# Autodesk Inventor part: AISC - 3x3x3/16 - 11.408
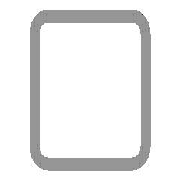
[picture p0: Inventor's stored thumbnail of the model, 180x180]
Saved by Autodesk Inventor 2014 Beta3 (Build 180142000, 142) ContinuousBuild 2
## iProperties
IsCustomPart: 1
Created: 2010-11
Part Number: AISC - 3x3x3/16 - 11.408
Material: Steel, Mild
Description: Tube
Document SubType Name: Modeling
Standard: ANSI
Designer: Beta-8540w
Standards Organization: ANSI
Language: en-US
Size Designation: 3x3x3/16
Categories: <MemberInstance><Categories><Category DisplayName="Structural Shapes" InternalName="089c4875-fa83-4c05-b084-43b9cc11f5ed" Mnemonic="GRDR"><CategoryParameter Dis
Stock Number: 3x3x3/16
Density: 7.86 g/cm^3
Appearance: Steel
G_L: 11.408 in
G_W: 3.000 in
G_H: 3.000 in
+F48483C9-E9F5-4C3B-A2E0-95EBE26CBBEF+CUTDETAIL1: Miter 45.00 deg
_CCFamilyMember: 9
_CCFamilyDisplayName: ANSI AISC (Square) - Tube
_FrameMemberDoc: Frame Member File
_Version: 15.0.0
_GetPNFromCC: 1
Author: Beta-8540w
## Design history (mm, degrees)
node "Start plane"
node "End plane"
sketch "Sketch"
  geometry: L1 (-38.1, -28.575)-(-38.1, 28.575); L2 (-28.575, 38.1)-(28.575, 38.1); L3 (38.1, 28.575)-(38.1, -28.575); L4 (28.575, -38.1)-(-28.575, -38.1); L5 (-28.575, 33.337)-(28.575, 33.338); L6 (33.338, 28.575)-(33.338, -28.575); L7 (28.575, -33.337)-(-28.575, -33.338); L8 (-33.338, -28.575)-(-33.338, 28.575); L9 (0, 56.102)-(0, -56.102) reference; L10 (-56.102, 0)-(56.102, 0) reference; A1 r 9.525 centre (-28.575, -28.575) between (-38.1, -28.575) and (-28.575, -38.1); A2 r 9.525 centre (-28.575, 28.575) between (-28.575, 38.1) and (-38.1, 28.575); A3 r 9.525 centre (28.575, 28.575) between (38.1, 28.575) and (28.575, 38.1); A4 r 9.525 centre (28.575, -28.575) between (28.575, -38.1) and (38.1, -28.575); A5 r 4.763 centre (-28.575, 28.575) between (-28.575, 33.337) and (-33.338, 28.575); A6 r 4.763 centre (28.575, 28.575) between (33.338, 28.575) and (28.575, 33.338); A7 r 4.763 centre (28.575, -28.575) between (28.575, -33.337) and (33.338, -28.575); A8 r 4.763 centre (-28.575, -28.575) between (-33.338, -28.575) and (-28.575, -33.338)
  constraints: 16 end point, 16 point on circle, 8 centre point, 8 tangent, 4 parallel, 3 equal radius, 2 perpendicular, 7 other
  dimensions: "d10" = 76.2 distance between parallel lines of L2 L4 (= G_H); "d11" = 76.2 distance between parallel lines of L1 L3 (= G_W); "d12" = 4.7625 distance between parallel lines of L3 L6 (= G_T); "d15" = 38.1 distance between parallel lines of L2 L10 (= 0.5 x d10); "d16" = 38.1 distance between parallel lines of L9 L3 (= 0.5 x d11); "d17" = 9.525 radius of A1 (= G_IR)
extrude "Body" new body sketch "Sketch" stored distance "d3" = 289.76513 (= G_L); taper "d4" = 0 deg
node "Driven Length"
  sketch "Sketch3"
    geometry: L1 (0, 0)-(10, 0) reference
    constraints: 2 end point, 1 horizontal
  workplane "Work Plane3"
  sketch "Sketch4"
    geometry: L1 (-2, 0)-(12, 0) reference; L2 (-2, 289.765)-(12, 289.765) reference
    dimensions: "d19" = 289.76513 distance between parallel lines of L1 L2 (derived)
workplane "Work Plane4"
split "Split1"
body "Solid1"
other parameters: "G_W" = 76.2 [user parameter; used in 1 equation term], "G_H" = 76.2 [user parameter; used in 1 equation term], "G_T" = 4.7625 [user parameter; used in 1 equation term], "G_IR" = 9.525 [user parameter; used in 1 equation term], "G_L" = 289.76513 (= d19) [user parameter; used in 1 equation term], "G_OFFSET_START" = 0 [user parameter; used in 1 equation term], "G_OFFSET_END" = 35.76513 [user parameter; used in 1 equation term], "d13" = 0 (computed from G_OFFSET_START), "d14" = 289.76513 (= G_OFFSET_END + B_L), "B_L" = 254 [user parameter; used in 1 equation term], "d18" = 90 deg
